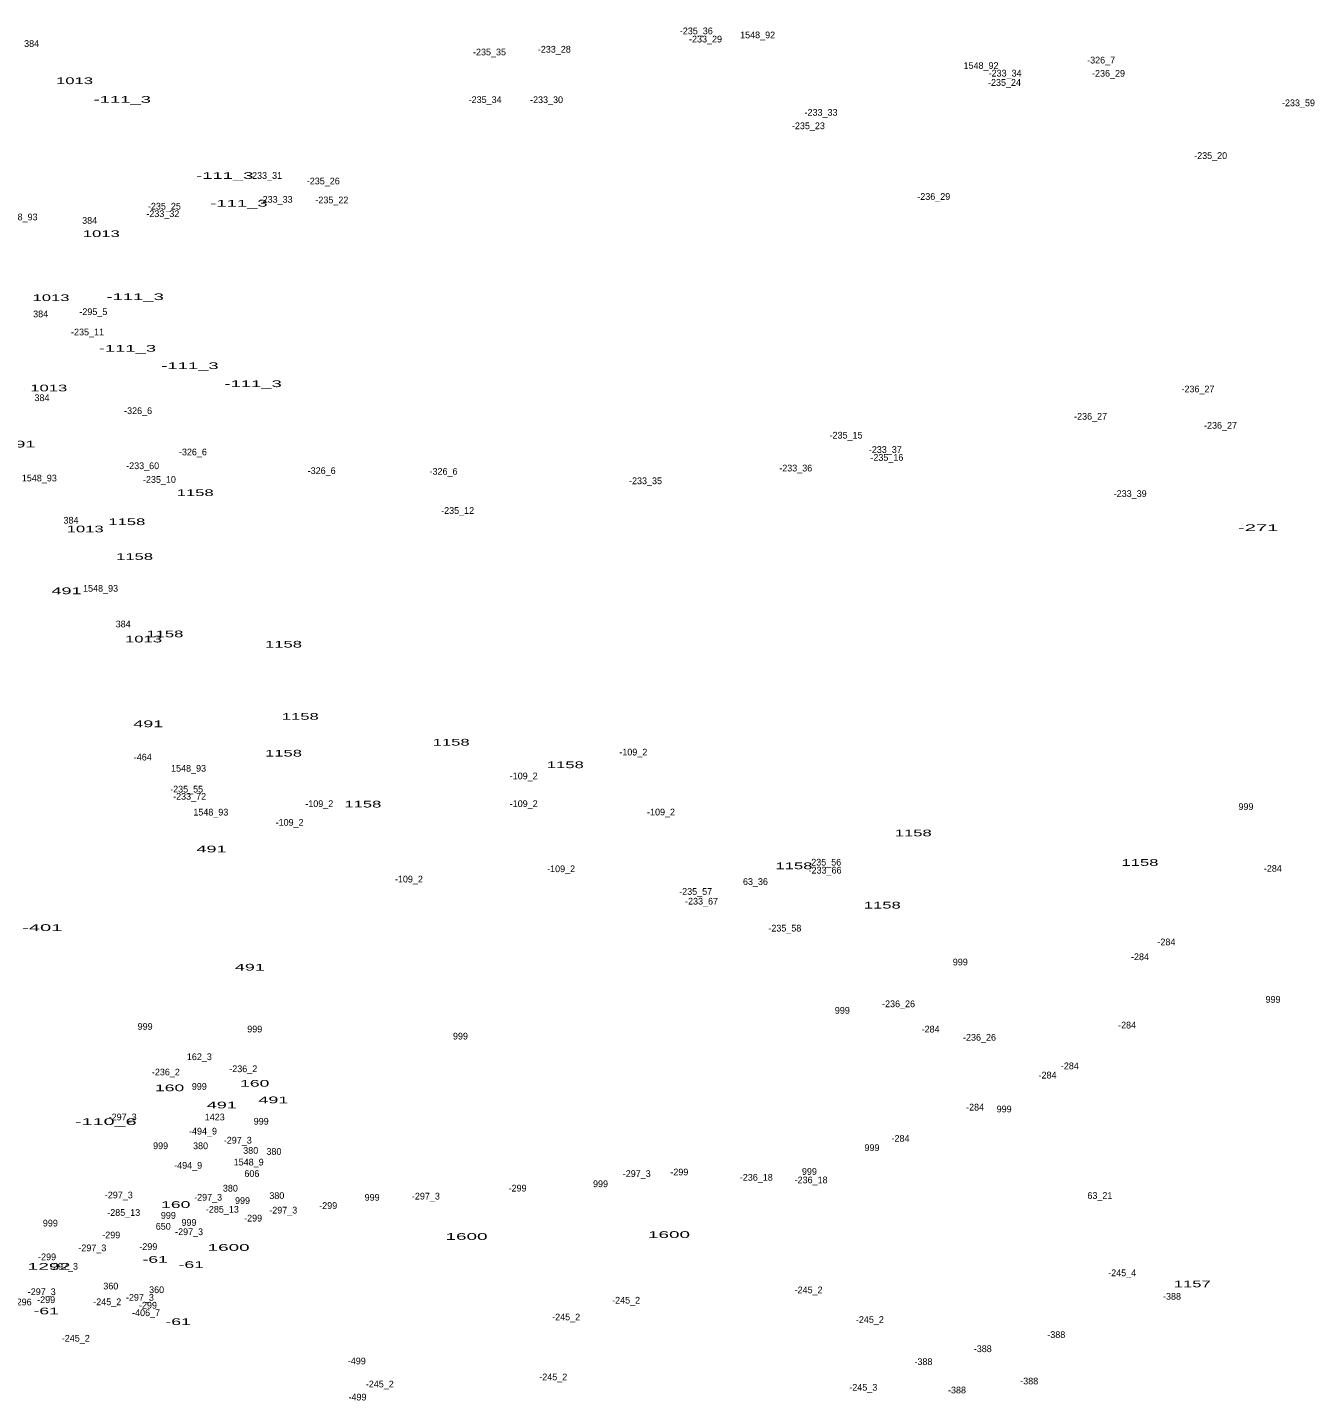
# Model space of a CAD drawing. Extents: x -660434 to -656144, y -997850 to -994016.
# Drawn here: x -657690 to -656923, y -996248 to -995430 of the extents above; entities that cross this region are included whole.
import ezdxf
from ezdxf.enums import TextEntityAlignment as Align

# ---------------------------------------------------------------- set-up
doc = ezdxf.new("R2010")
doc.units = 0
doc.header["$LTSCALE"] = 1.6
doc.layers.add('24', color=7, linetype='Continuous')

msp = doc.modelspace()

# ---------------------------------------------------------------- texts
at = {"layer": '24'}
for s, p in [('-235_36', (-657291.517, -995433.61)), ('384', (-657687.371, -995441.14)), ('-233_29', (-657286.027, -995438.48)), ('1548_92', (-657255.017, -995436)), ('-235_35', (-657414.681, -995446.19)), ('-233_28', (-657376.071, -995444.53)), ('-326_7', (-657050.434, -995451.01)), ('1548_92', (-657121.957, -995454.25)), ('-233_34', (-657107.616, -995458.79)), ('-236_29', (-657046.032, -995458.89)), ('-235_24', (-657107.986, -995464.33)), ('-235_34', (-657417.296, -995474.56)), ('-233_30', (-657380.705, -995474.62)), ('-233_33', (-657217.251, -995482.13)), ('-233_59', (-656932.907, -995476.47)), ('-235_23', (-657224.761, -995490.15)), ('-235_20', (-656985.205, -995507.88)), ('-233_31', (-657548.045, -995519.76)), ('-235_26', (-657513.677, -995523.03)), ('-236_29', (-657150.102, -995532.26)), ('-235_25', (-657608.291, -995538.04)), ('-233_33', (-657541.751, -995533.98)), ('-235_22', (-657508.541, -995534.34)), ('1548_93', (-657694.227, -995544.44)), ('384', (-657652.811, -995546.52)), ('-233_32', (-657609.231, -995542.53)), ('384', (-657681.991, -995602.23)), ('-295_5', (-657650.598, -995600.91)), ('-235_11', (-657654.069, -995613.02)), ('-236_27', (-656992.773, -995646.94)), ('384', (-657681.221, -995652.17)), ('-326_6', (-657623.963, -995659.91)), ('-236_27', (-657056.713, -995663.27)), ('-236_27', (-656979.333, -995668.64)), ('-235_15', (-657202.325, -995674.49)), ('-326_6', (-657591.313, -995684.49)), ('-233_37', (-657178.947, -995683.03)), ('-235_16', (-657178.031, -995687.74)), ('-233_60', (-657621.241, -995692.7)), ('-326_6', (-657514.633, -995695.63)), ('-326_6', (-657442.053, -995696.02)), ('-233_36', (-657232.307, -995694.08)), ('1548_93', (-657682.787, -995700.02)), ('-235_10', (-657611.249, -995700.86)), ('-233_35', (-657321.771, -995701.66)), ('-233_39', (-657033.127, -995709.26)), ('-235_12', (-657433.665, -995719.35)), ('384', (-657663.941, -995725.16)), ('1548_93', (-657646.307, -995765.71)), ('384', (-657632.841, -995787)), ('-464', (-657621.189, -995866.29)), ('-109_2', (-657329.036, -995863.3)), ('1548_93', (-657593.897, -995872.96)), ('-109_2', (-657394.316, -995877.51)), ('-235_55', (-657595.061, -995885.36)), ('-233_72', (-657593.287, -995889.67)), ('1548_93', (-657580.647, -995899.08)), ('-109_2', (-657516.056, -995894.03)), ('-109_2', (-657394.316, -995894.03)), ('-109_2', (-657312.526, -995899.02)), ('999', (-656964.173, -995895.78)), ('-109_2', (-657533.716, -995905.17)), ('-109_2', (-657372.046, -995932.83)), ('-235_56', (-657215.047, -995928.9)), ('-233_66', (-657214.862, -995933.65)), ('-284', (-656948.189, -995932.61)), ('-109_2', (-657462.676, -995938.97)), ('63_36', (-657256.296, -995940.42)), ('-235_57', (-657291.917, -995946.33)), ('-233_67', (-657288.403, -995952.13)), ('-235_58', (-657238.791, -995968.19)), ('-284', (-657011.549, -995976.4)), ('999', (-657134.293, -995988.36)), ('-284', (-657027.299, -995985.24)), ('-236_26', (-657171.072, -996013.28)), ('999', (-656948.043, -996010.64)), ('999', (-657204.563, -996017.17)), ('999', (-657619.763, -996026.77)), ('999', (-657554.483, -996028.31)), ('-284', (-657152.009, -996028.35)), ('-284', (-657034.979, -996025.96)), ('999', (-657431.973, -996032.53)), ('-236_26', (-657122.872, -996033.26)), ('162_3', (-657587.464, -996044.82)), ('-236_2', (-657607.408, -996053.92)), ('-236_2', (-657561.328, -996051.99)), ('-284', (-657082.359, -996055.77)), ('-284', (-657069.059, -996050.25)), ('999', (-657587.503, -996062.5)), ('-297_3', (-657633.144, -996080.7)), ('1423', (-657578.314, -996080.72)), ('-284', (-657125.509, -996074.84)), ('999', (-657108.183, -996075.94)), ('-494_9', (-657585.312, -996089.15)), ('999', (-657550.643, -996083.24)), ('999', (-657610.543, -996097.84)), ('380', (-657586.751, -996097.87)), ('-297_3', (-657564.594, -996094.53)), ('-284', (-657169.919, -996093.42)), ('380', (-657556.891, -996100.65)), ('380', (-657543.071, -996101.23)), ('999', (-657186.903, -996098.99)), ('-494_9', (-657594.142, -996109.51)), ('1548_9', (-657558.098, -996107.59)), ('-299', (-657301.615, -996113.5)), ('999', (-657224.153, -996113.2)), ('606', (-657556.202, -996114.36)), ('999', (-657348.573, -996120.5)), ('-297_3', (-657326.994, -996114.42)), ('-236_18', (-657255.791, -996116.65)), ('-236_18', (-657223.151, -996118.19)), ('-297_3', (-657635.444, -996127.18)), ('-297_3', (-657582.264, -996128.53)), ('380', (-657568.991, -996123.13)), ('999', (-657561.773, -996130.49)), ('380', (-657541.341, -996127.55)), ('999', (-657484.583, -996128.57)), ('-297_3', (-657452.564, -996127.87)), ('-299', (-657397.945, -996123.11)), ('63_21', (-657051.164, -996127.5)), ('-285_13', (-657632.515, -996137.61)), ('-285_13', (-657573.765, -996135.69)), ('-297_3', (-657537.524, -996136.21)), ('-299', (-657510.735, -996133.48)), ('999', (-657676.213, -996143.94)), ('650', (-657608.977, -996145.86)), ('999', (-657605.933, -996139.33)), ('999', (-657593.643, -996143.55)), ('-299', (-657555.465, -996140.97)), ('-299', (-657639.955, -996150.98)), ('-297_3', (-657593.594, -996149.08)), ('-297_3', (-657651.194, -996158.68)), ('-299', (-657617.875, -996157.9)), ('-299', (-657678.165, -996164.04)), ('-297_3', (-657668.094, -996169.63)), ('-245_4', (-657037.901, -996173.55)), ('-297_3', (-657681.334, -996184.81)), ('360', (-657640.197, -996181.43)), ('360', (-657612.937, -996183.64)), ('-245_2', (-657224.647, -996183.72)), ('-388', (-657008.215, -996187.56)), ('-296', (-657692.705, -996190.95)), ('-299', (-657678.705, -996189.58)), ('-245_2', (-657642.347, -996190.82)), ('-297_3', (-657622.874, -996188.17)), ('-299', (-657618.085, -996192.86)), ('-245_2', (-657333.327, -996189.87)), ('-406_7', (-657619.212, -996197.34)), ('-245_2', (-657369.037, -996199.85)), ('-245_2', (-657188.167, -996201.39)), ('-388', (-657077.145, -996210.34)), ('-245_2', (-657661.077, -996212.53)), ('-388', (-657120.925, -996218.79)), ('-499', (-657493.709, -996226.07)), ('-388', (-657156.255, -996226.48)), ('-245_2', (-657376.717, -996235.58)), ('-245_2', (-657480.017, -996239.81)), ('-245_3', (-657192.077, -996241.77)), ('-388', (-657136.285, -996243.38)), ('-388', (-657093.275, -996238)), ('-499', (-657493.319, -996247.58))]:
    msp.add_text(s, height=4, dxfattribs=at).set_placement(p, align=Align.CENTER)
for s, width, p in [('1013', 1.85, (-657661.8, -995463.31)), ('-111_3', 2.05, (-657633.394, -995474.44)), ('-111_3', 2.05, (-657572.344, -995519.77)), ('-111_3', 2.05, (-657563.894, -995536.27)), ('1013', 1.85, (-657645.86, -995554.43)), ('1013', 1.85, (-657675.81, -995592.57)), ('-111_3', 2.05, (-657625.714, -995591.99)), ('-111_3', 2.05, (-657630.324, -995622.72)), ('-111_3', 2.05, (-657593.074, -995633.09)), ('1013', 1.85, (-657677.16, -995646.36)), ('-111_3', 2.05, (-657555.444, -995643.83)), ('491', 2, (-657694.048, -995679.8)), ('1158', 1.85, (-657589.964, -995708.75)), ('1158', 1.85, (-657630.664, -995726.04)), ('-271', 2.25, (-656956.875, -995729.58)), ('1013', 1.85, (-657655.46, -995730.35)), ('1158', 1.85, (-657626.054, -995746.78)), ('491', 2, (-657666.588, -995767.2)), ('1158', 1.85, (-657608.004, -995792.88)), ('1013', 1.85, (-657620.71, -995795.96)), ('1158', 1.85, (-657537.354, -995799.03)), ('1158', 1.85, (-657527.364, -995842.05)), ('491', 2, (-657617.898, -995846.45)), ('1158', 1.85, (-657437.504, -995857.42)), ('1158', 1.85, (-657537.354, -995863.95)), ('1158', 1.85, (-657369.534, -995870.86)), ('1158', 1.85, (-657490.114, -995894.3)), ('1158', 1.85, (-657162.324, -995911.47)), ('491', 2, (-657580.258, -995921.06)), ('1158', 1.85, (-657233.364, -995931.06)), ('1158', 1.85, (-657027.304, -995929.07)), ('1158', 1.85, (-657180.754, -995954.5)), ('-401', 2.25, (-657681.022, -995967.85)), ('491', 2, (-657557.408, -995991.46)), ('160', 1.95, (-657605.179, -996063.34)), ('160', 1.95, (-657554.489, -996060.65)), ('491', 2, (-657543.388, -996070.5)), ('491', 2, (-657574.118, -996073.58)), ('-110_6', 2.2, (-657643.189, -996083.45)), ('160', 1.95, (-657601.529, -996132.87)), ('1600', 2.1, (-657428.355, -996151.91)), ('1600', 2.1, (-657307.775, -996150.76)), ('1600', 2.1, (-657570.055, -996158.44)), ('1292', 2.15, (-657677.053, -996169.75)), ('-61', 1.95, (-657613.785, -996165.57)), ('-61', 1.95, (-657592.285, -996168.64)), ('1157', 1.85, (-656996.169, -996180.14)), ('-61', 1.95, (-657678.685, -996196.29)), ('-61', 1.95, (-657600.145, -996202.64))]:
    msp.add_text(s, height=4, dxfattribs=dict(at, width=width)).set_placement(p, align=Align.CENTER)

doc.saveas('drawing.dxf')
